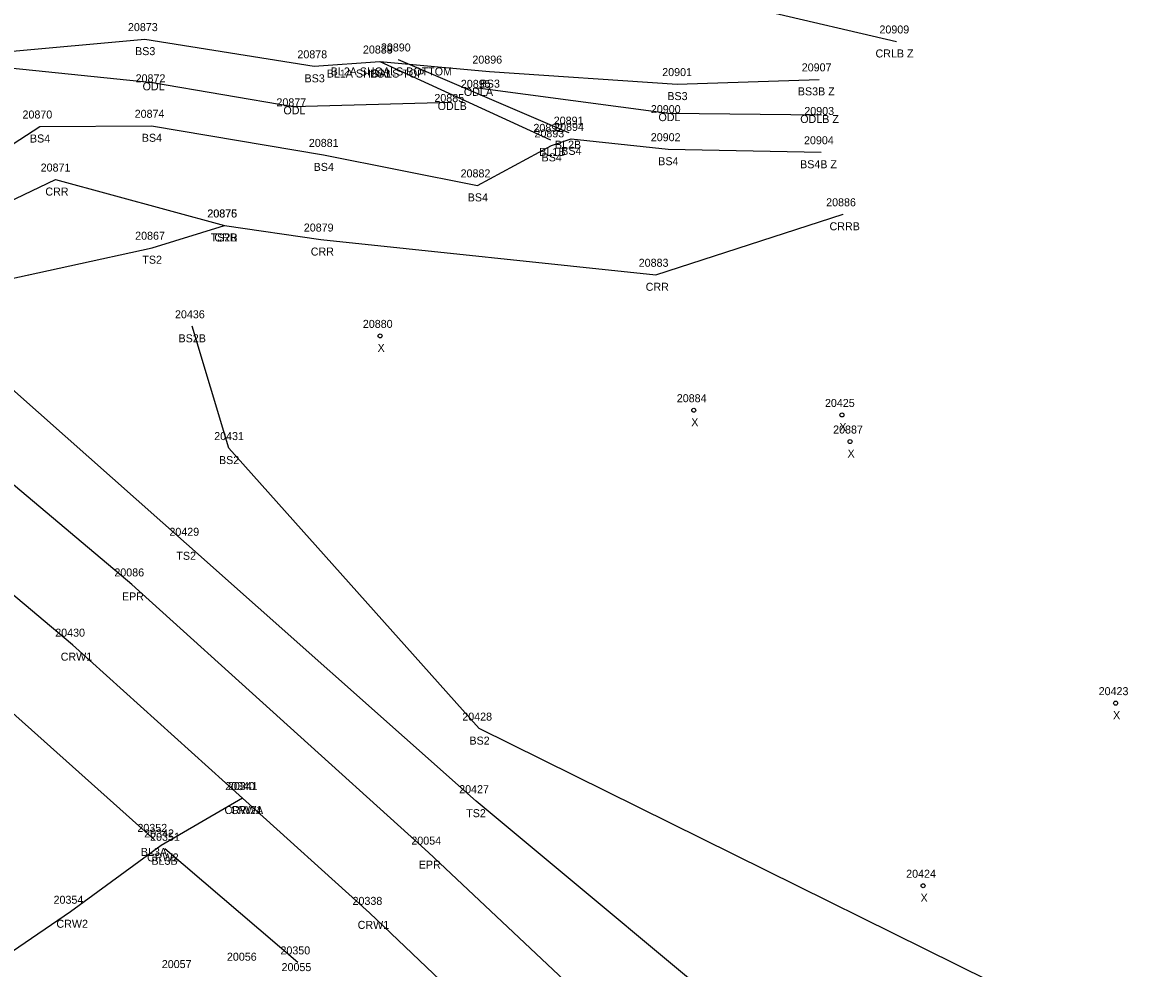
# Model space of a CAD drawing. Extents: x 1813127 to 1814107, y 1178171 to 1179078.
# Drawn here: x 1813803.8 to 1813944.8, y 1178622 to 1178740.3 of the extents above; entities that cross this region are included whole.
import ezdxf

# ---------------------------------------------------------------- set-up
doc = ezdxf.new("R2010")
doc.units = 0
for name, color, linetype in [('RD_DTM_BkLn1', 7, 'Continuous'), ('RD_DTM_BkLn2', 7, 'Continuous'), ('RD_EX_H2O', 7, 'Continuous'), ('RD_EX_H2O_txCode', 7, 'Continuous'), ('RD_EX_Road', 7, 'Continuous'), ('RD_EX_Road_txCode', 7, 'Continuous'), ('RD_SMD_Locator', 7, 'Continuous'), ('RD_SMD_Misc', 7, 'Continuous')]:
    doc.layers.add(name, color=color, linetype=linetype)

msp = doc.modelspace()

# ---------------------------------------------------------------- linework, layer by layer
at = {"layer": 'RD_DTM_BkLn1'}
for p, q in [((1813848.44, 1178735.38), (1813869.76, 1178725.59)), ((1813850.74, 1178735.64), (1813872.01, 1178726.49)), ((1813820.26, 1178638.1), (1813802.14, 1178654.3)), ((1813838.18, 1178622.79), (1813821.57, 1178636.99))]:
    msp.add_line(p, q, dxfattribs=at)
for points in [[(1814069.63, 1178419.56), (1814043.03, 1178443.95), (1814031.76, 1178453.98), (1813994.68, 1178489.07), (1813958.14, 1178523.5), (1813920.87, 1178558.86), (1813884.46, 1178593.47), (1813847.15, 1178628.98), (1813831.28, 1178643.33), (1813810.03, 1178662.5), (1813772.7, 1178693.86)], [(1813831.28, 1178643.33), (1813821.11, 1178637.41), (1813809.78, 1178629.12), (1813788.78, 1178614.79), (1813747.67, 1178586.85), (1813706.5, 1178558.14), (1813665.11, 1178528), (1813623.37, 1178496.83), (1813582.75, 1178466.66)]]:
    msp.add_lwpolyline(points, dxfattribs=at)
at = {"layer": 'RD_DTM_BkLn2'}
for points in [[(1813501.61, 1178700.78), (1813535.62, 1178707.92), (1813578.65, 1178686.08), (1813588.2, 1178681.74), (1813622.61, 1178682.2), (1813653.79, 1178685.74), (1813685.17, 1178685.29), (1813723.1, 1178689.85), (1813736.83, 1178692.71), (1813771.26, 1178719.75), (1813784.46, 1178726.39), (1813801.14, 1178736.57), (1813819.08, 1178738.18), (1813840.25, 1178734.78), (1813848.44, 1178735.38), (1813862.15, 1178734.12), (1813885.61, 1178732.56), (1813903.34, 1178733.15)], [(1813494.55, 1178680.43), (1813533.86, 1178695.27), (1813573.03, 1178675.94), (1813630.33, 1178669.28), (1813656.92, 1178672.11), (1813691.39, 1178675.03), (1813721.31, 1178671.27), (1813738.7, 1178671.81), (1813780.2, 1178710.54), (1813805.93, 1178727.26), (1813819.91, 1178727.35), (1813841.4, 1178723.71), (1813860.66, 1178719.9), (1813869.89, 1178724.9), (1813872.35, 1178725.71), (1813884.47, 1178724.42), (1813903.61, 1178724.04)], [(1813780.61, 1178703.45), (1813789.06, 1178705.34), (1813820, 1178712.11), (1813829.02, 1178714.89)], [(1814080.77, 1178431.89), (1814053.55, 1178456.53), (1814053.55, 1178456.53), (1814043.11, 1178466.04), (1814008.23, 1178502.68), (1813981.17, 1178545.08), (1813940.17, 1178583.78), (1813898.27, 1178611.44), (1813860.48, 1178642.94), (1813824.26, 1178675.11), (1813790.56, 1178704.96), (1813785.53, 1178702.33), (1813780.61, 1178703.45)], [(1814084.95, 1178436.37), (1814047.91, 1178471.1), (1814016.08, 1178513.45), (1813993.35, 1178553.48), (1813952.47, 1178606.71), (1813860.87, 1178652.01), (1813829.57, 1178687.07), (1813824.98, 1178702.29)]]:
    msp.add_lwpolyline(points, dxfattribs=at)
at = {"layer": 'RD_EX_H2O'}
for points in [[(1813767.83, 1178739.34), (1813802.7, 1178746.65), (1813832.24, 1178749.11), (1813880.12, 1178745.59), (1813913.04, 1178737.89)], [(1813497.15, 1178691.5), (1813535.61, 1178703.5), (1813575.96, 1178680.52), (1813619.86, 1178677.62), (1813650.02, 1178676.71), (1813688.26, 1178680.15), (1813722.87, 1178676.67), (1813738.45, 1178684.24), (1813776.33, 1178715.9), (1813785.2, 1178724.07), (1813802.21, 1178734.6), (1813820.03, 1178732.78), (1813837.63, 1178729.78), (1813857.38, 1178730.32)], [(1813860.69, 1178732.09), (1813884.52, 1178728.93), (1813903.65, 1178728.7)], [(1813747.03, 1178677.41), (1813754.34, 1178684.8), (1813763.95, 1178688.13), (1813782.12, 1178708.31), (1813807.89, 1178720.63), (1813829.02, 1178714.89), (1813841.06, 1178713.13), (1813882.92, 1178708.73), (1813906.37, 1178716.29)]]:
    msp.add_lwpolyline(points, dxfattribs=at)
at = {"layer": 'RD_EX_Road'}
msp.add_lwpolyline([(1814076.45, 1178427.4), (1814038.86, 1178461.87), (1814001.83, 1178496.62), (1813965.15, 1178531.54), (1813928.08, 1178567.1), (1813892.01, 1178601.23), (1813854.54, 1178636.51), (1813817.44, 1178670.03), (1813779.87, 1178701.64)], dxfattribs=at)
at = {"layer": 'RD_SMD_Locator'}
for centre, radius in [((1813819.08, 1178738.18), 0.001), ((1813913.04, 1178737.89), 0.001), ((1813840.25, 1178734.78), 0.001), ((1813848.44, 1178735.38), 0.001), ((1813848.44, 1178735.38), 0.001), ((1813850.74, 1178735.64), 0.001), ((1813862.15, 1178734.12), 0.001), ((1813820.03, 1178732.78), 0.001), ((1813860.69, 1178732.09), 0.001), ((1813885.61, 1178732.56), 0.001), ((1813903.34, 1178733.15), 0.001), ((1813837.63, 1178729.78), 0.001), ((1813857.38, 1178730.32), 0.001), ((1813884.52, 1178728.93), 0.001), ((1813903.65, 1178728.7), 0.001), ((1813805.93, 1178727.26), 0.001), ((1813819.91, 1178727.35), 0.001), ((1813872.01, 1178726.49), 0.001), ((1813869.76, 1178725.59), 0.001), ((1813869.89, 1178724.9), 0.001), ((1813872.35, 1178725.71), 0.001), ((1813841.4, 1178723.71), 0.001), ((1813884.47, 1178724.42), 0.001), ((1813903.61, 1178724.04), 0.001), ((1813807.89, 1178720.63), 0.001), ((1813860.66, 1178719.9), 0.001), ((1813906.37, 1178716.29), 0.001), ((1813829.02, 1178714.89), 0.001), ((1813829.02, 1178714.89), 0.001), ((1813820, 1178712.11), 0.001), ((1813841.06, 1178713.13), 0.001), ((1813882.92, 1178708.73), 0.001), ((1813824.98, 1178702.29), 0.001), ((1813848.48, 1178701.09), 0.25), ((1813887.68, 1178691.8), 0.25), ((1813906.2, 1178691.21), 0.25), ((1813907.21, 1178687.89), 0.25), ((1813829.57, 1178687.07), 0.001), ((1813824.26, 1178675.11), 0.001), ((1813817.44, 1178670.03), 0.001), ((1813810.03, 1178662.5), 0.001), ((1813940.41, 1178655.19), 0.25), ((1813860.87, 1178652.01), 0.001), ((1813831.28, 1178643.33), 0.001), ((1813831.28, 1178643.33), 0.001), ((1813860.48, 1178642.94), 0.001), ((1813820.26, 1178638.1), 0.001), ((1813821.11, 1178637.41), 0.001), ((1813821.57, 1178636.99), 0.001), ((1813854.54, 1178636.51), 0.001), ((1813916.35, 1178632.37), 0.25), ((1813809.78, 1178629.12), 0.001), ((1813847.15, 1178628.98), 0.001), ((1813838.18, 1178622.79), 0.001)]:
    msp.add_circle(centre, radius, dxfattribs=at)

# ---------------------------------------------------------------- texts
at = {"layer": 'RD_EX_H2O_txCode'}
for s, p in [('20909', (1813910.89, 1178738.89)), ('CRLB Z', (1813910.4, 1178735.89)), ('20872', (1813817.92, 1178732.78)), ('ODL', (1813818.79, 1178731.78)), ('20895', (1813858.57, 1178732.09)), ('ODLA', (1813858.95, 1178731.09)), ('20877', (1813835.52, 1178729.78)), ('20885', (1813855.26, 1178730.32)), ('ODL', (1813836.39, 1178728.78)), ('ODLB', (1813855.67, 1178729.32)), ('20900', (1813882.32, 1178728.93)), ('ODL', (1813883.27, 1178727.93)), ('20903', (1813901.5, 1178728.7)), ('ODLB Z', (1813900.99, 1178727.7)), ('20871', (1813806.05, 1178721.63)), ('CRR', (1813806.63, 1178718.63)), ('20886', (1813904.23, 1178717.29)), ('20876', (1813826.87, 1178715.89)), ('20879', (1813838.94, 1178714.13)), ('CRRB', (1813904.65, 1178714.29)), ('CRR', (1813827.76, 1178712.89)), ('CRR', (1813839.81, 1178711.13)), ('20883', (1813880.8, 1178709.73)), ('CRR', (1813881.67, 1178706.73))]:
    msp.add_text(s, height=1, dxfattribs=at).set_placement(p)
at = {"layer": 'RD_EX_Road_txCode'}
for s, p in [('20086', (1813815.26, 1178671.03)), ('EPR', (1813816.21, 1178668.03)), ('20054', (1813852.38, 1178637.51)), ('EPR', (1813853.31, 1178634.51)), ('20056', (1813829.33, 1178623)), ('20057', (1813821.19, 1178622.08)), ('20055', (1813836.16, 1178621.7))]:
    msp.add_text(s, height=1, dxfattribs=at).set_placement(p)
at = {"layer": 'RD_SMD_Misc'}
for s, p in [('20873', (1813816.96, 1178739.18)), ('20888', (1813846.33, 1178736.38)), ('20889', (1813846.33, 1178736.38)), ('20890', (1813848.58, 1178736.64)), ('BS3', (1813817.85, 1178736.18)), ('20878', (1813838.14, 1178735.78)), ('20896', (1813860.01, 1178735.12)), ('BL2A SHOALS BOTTOM', (1813842.3, 1178733.64)), ('20901', (1813883.74, 1178733.56)), ('20907', (1813901.18, 1178734.15)), ('BS3', (1813839.03, 1178732.78)), ('BL1A SHOALS TOP', (1813841.81, 1178733.38)), ('BS3', (1813847.22, 1178733.38)), ('BS3', (1813860.92, 1178732.12)), ('BS3B Z', (1813900.69, 1178731.15)), ('BS3', (1813884.38, 1178730.56)), ('20870', (1813803.78, 1178728.26)), ('20874', (1813817.8, 1178728.35)), ('20892', (1813867.64, 1178726.59)), ('20891', (1813870.18, 1178727.49)), ('20894', (1813870.23, 1178726.71)), ('BS4', (1813804.71, 1178725.26)), ('BS4', (1813818.69, 1178725.35)), ('20893', (1813867.77, 1178725.9)), ('20902', (1813882.31, 1178725.42)), ('20881', (1813839.57, 1178724.71)), ('BL2B', (1813870.33, 1178724.49)), ('BS4', (1813871.12, 1178723.71)), ('20904', (1813901.46, 1178725.04)), ('BL1B', (1813868.37, 1178723.59)), ('BS4', (1813868.66, 1178722.9)), ('BS4', (1813883.24, 1178722.42)), ('BS4', (1813840.17, 1178721.71)), ('20882', (1813858.54, 1178720.9)), ('BS4B Z', (1813900.97, 1178722.04)), ('BS4', (1813859.43, 1178717.9)), ('20875', (1813826.9, 1178715.89)), ('20867', (1813817.86, 1178713.11)), ('TS2B', (1813827.3, 1178712.89)), ('TS2', (1813818.76, 1178710.11)), ('20436', (1813822.84, 1178703.29)), ('20880', (1813846.32, 1178702.09)), ('BS2B', (1813823.28, 1178700.29)), ('X', (1813848.16, 1178699.09)), ('20884', (1813885.56, 1178692.8)), ('20425', (1813904.08, 1178692.21)), ('X', (1813887.37, 1178689.8)), ('20887', (1813905.1, 1178688.89)), ('X', (1813905.88, 1178689.21)), ('20431', (1813827.74, 1178688.07)), ('X', (1813906.9, 1178685.89)), ('BS2', (1813828.34, 1178685.07)), ('20429', (1813822.14, 1178676.11)), ('TS2', (1813823.01, 1178673.11)), ('20430', (1813807.87, 1178663.5)), ('CRW1', (1813808.55, 1178660.5)), ('20423', (1813938.29, 1178656.19)), ('20428', (1813858.75, 1178653.01)), ('X', (1813940.09, 1178653.19)), ('BS2', (1813859.64, 1178650.01)), ('20340', (1813829.12, 1178644.33)), ('20341', (1813829.45, 1178644.33)), ('20427', (1813858.36, 1178643.94)), ('CRW2A', (1813829.03, 1178641.33)), ('CRW1', (1813829.8, 1178641.33)), ('TS2', (1813859.24, 1178640.94)), ('20352', (1813818.14, 1178639.1)), ('20342', (1813818.99, 1178638.41)), ('20351', (1813819.73, 1178637.99)), ('BL3A', (1813818.57, 1178636.1)), ('CRW2', (1813819.35, 1178635.41)), ('BL3B', (1813819.89, 1178634.99)), ('20424', (1813914.23, 1178633.37)), ('20354', (1813807.66, 1178630.12)), ('20338', (1813845.03, 1178629.98)), ('X', (1813916.03, 1178630.37)), ('CRW2', (1813808.02, 1178627.12)), ('CRW1', (1813845.67, 1178626.98)), ('20350', (1813836.02, 1178623.79))]:
    msp.add_text(s, height=1, dxfattribs=at).set_placement(p)

doc.saveas('drawing.dxf')
